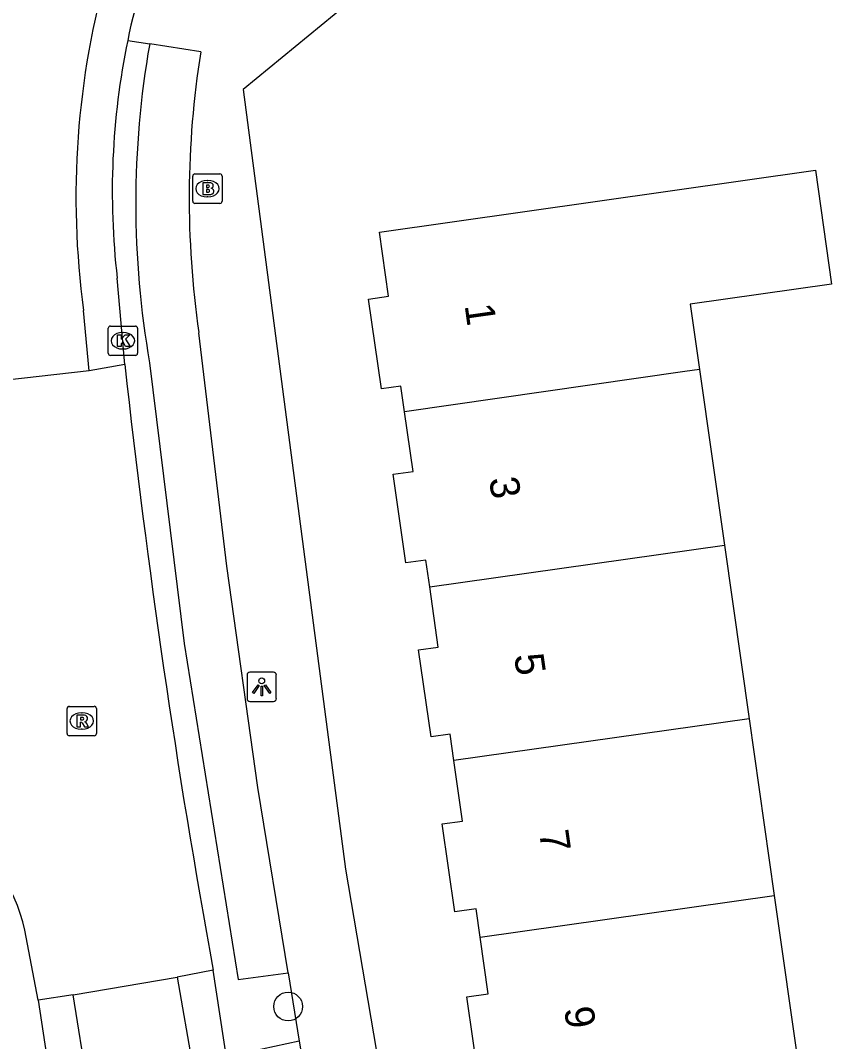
# Model space of a CAD drawing. Extents: x 162074 to 163034, y 381824 to 382557.
# Drawn here: x 162471.78 to 162499.41, y 382456.46 to 382491.25 of the extents above; entities that cross this region are included whole.
import ezdxf

# ---------------------------------------------------------------- set-up
doc = ezdxf.new("R2010")
doc.units = 0
for name, color, linetype in [('IMGEO_Boom', 7, 'Continuous'), ('IMGEO_Brandkraan', 7, 'Continuous'), ('IMGEO_Fietspad_gesloten', 7, 'Continuous'), ('IMGEO_Kolk', 7, 'Continuous'), ('IMGEO_Lichtpunt', 7, 'Continuous'), ('IMGEO_Pand', 7, 'Continuous'), ('IMGEO_Pand_nummerreeks', 7, 'Continuous'), ('IMGEO_Rijbaan_lokaal_open', 7, 'Continuous'), ('IMGEO_Rioolput', 7, 'Continuous'), ('IMGEO_Voetpad_open', 7, 'Continuous')]:
    doc.layers.add(name, color=color, linetype=linetype)

msp = doc.modelspace()

# ---------------------------------------------------------------- linework, layer by layer
at = {"layer": 'IMGEO_Boom'}
msp.add_circle((162480.9, 382457.654), 0.489, dxfattribs=at)
at = {"layer": 'IMGEO_Brandkraan'}
for p, q in [((162477.725, 382486.019), (162478.577, 382486.019)), ((162477.65, 382485.093), (162477.65, 382485.945)), ((162478.138, 382485.799), (162478.163, 382485.799)), ((162478.651, 382485.945), (162478.651, 382485.093)), ((162478.577, 382485.019), (162477.725, 382485.019)), ((162478.161, 382485.239), (162478.136, 382485.239))]:
    msp.add_line(p, q, dxfattribs=at)
for points in [[(162477.725, 382486.019), (162478.577, 382486.019)], [(162477.65, 382485.093), (162477.65, 382485.945)], [(162477.998, 382485.719), (162477.998, 382485.319), (162478.211, 382485.319)], [(162478.229, 382485.719), (162477.998, 382485.719)], [(162478.651, 382485.945), (162478.651, 382485.093)], [(162478.177, 382485.638), (162478.123, 382485.638), (162478.123, 382485.562)], [(162478.123, 382485.562), (162478.176, 382485.562)], [(162478.185, 382485.486), (162478.123, 382485.486), (162478.123, 382485.405)], [(162478.123, 382485.405), (162478.185, 382485.405)], [(162478.577, 382485.019), (162477.725, 382485.019)]]:
    msp.add_lwpolyline(points, dxfattribs=at)
for centre, radius, start, end in [((162477.727, 382485.943), 0.0765, 91.552, 178.448), ((162477.727, 382485.943), 0.0765, 91.552, 178.448), ((162478.575, 382485.943), 0.0765, 1.552, 88.448), ((162478.575, 382485.943), 0.0765, 1.552, 88.448), ((162478.233, 382485.574), 0.145, 59.4692, 91.5367), ((162478.258, 382485.621), 0.0922, 285.5137, 58.1501), ((162478.178, 382485.6), 0.0379, 267.8285, 90.9355), ((162478.186, 382485.445), 0.0404, 269.8759, 90.5077), ((162478.217, 382485.57), 0.251, 268.6676, 293.5347), ((162478.263, 382485.429), 0.105, 301.3115, 78.989), ((162477.727, 382485.095), 0.0765, 181.552, 268.448), ((162477.727, 382485.095), 0.0765, 181.552, 268.448), ((162478.575, 382485.095), 0.0765, 271.552, 358.448), ((162478.575, 382485.095), 0.0765, 271.552, 358.448)]:
    msp.add_arc(centre, radius, start, end, dxfattribs=at)
for centre, major_axis, ratio, start_param, end_param in [((162478.137, 382485.519), (-0.387, 0.002), 0.722429, 4.712389, 7.853982), ((162478.162, 382485.519), (-0.39, 0.002), 0.717154, 1.570796, 4.712389)]:
    msp.add_ellipse(centre, major_axis=major_axis, ratio=ratio, start_param=start_param, end_param=end_param, dxfattribs=at)
at = {"layer": 'IMGEO_Fietspad_gesloten'}
for points in [[(162475.335, 382479.532), (162475.076, 382482.472)], [(162478.823, 382455.767), (162478.345, 382458.898)], [(162472.383, 382457.868), (162472.865, 382454.723)]]:
    msp.add_lwpolyline(points, dxfattribs=at)
for centre, radius, start, end in [((162496.04, 382486.354), 21.033, 145.3205, 168.4412), ((162500.479, 382485.405), 25.571, 168.3507, 186.5854)]:
    msp.add_arc(centre, radius, start, end, dxfattribs=at)
at = {"layer": 'IMGEO_Kolk'}
for p, q in [((162474.846, 382480.837), (162475.698, 382480.837)), ((162474.771, 382479.911), (162474.771, 382480.763)), ((162475.259, 382480.617), (162475.284, 382480.617)), ((162475.772, 382480.763), (162475.772, 382479.911)), ((162475.698, 382479.837), (162474.846, 382479.837)), ((162475.282, 382480.057), (162475.257, 382480.057))]:
    msp.add_line(p, q, dxfattribs=at)
for points in [[(162474.846, 382480.837), (162475.698, 382480.837)], [(162474.771, 382479.911), (162474.771, 382480.763)], [(162475.092, 382480.537), (162475.215, 382480.537), (162475.215, 382480.386), (162475.345, 382480.537), (162475.509, 382480.537), (162475.363, 382480.386), (162475.516, 382480.137), (162475.364, 382480.137), (162475.279, 382480.301), (162475.215, 382480.234), (162475.215, 382480.137), (162475.092, 382480.137), (162475.092, 382480.537)], [(162475.772, 382480.763), (162475.772, 382479.911)], [(162475.698, 382479.837), (162474.846, 382479.837)]]:
    msp.add_lwpolyline(points, dxfattribs=at)
for centre, start, end in [((162474.848, 382480.761), 91.552, 178.448), ((162474.848, 382480.761), 91.552, 178.448), ((162475.696, 382480.761), 1.552, 88.448), ((162475.696, 382480.761), 1.552, 88.448), ((162474.848, 382479.913), 181.552, 268.448), ((162474.848, 382479.913), 181.552, 268.448), ((162475.696, 382479.913), 271.552, 358.448), ((162475.696, 382479.913), 271.552, 358.448)]:
    msp.add_arc(centre, 0.0765, start, end, dxfattribs=at)
for centre, major_axis, ratio, start_param, end_param in [((162475.258, 382480.337), (-0.387, 0.002), 0.722429, 4.712389, 7.853982), ((162475.283, 382480.337), (-0.39, 0.002), 0.717154, 1.570796, 4.712389)]:
    msp.add_ellipse(centre, major_axis=major_axis, ratio=ratio, start_param=start_param, end_param=end_param, dxfattribs=at)
at = {"layer": 'IMGEO_Lichtpunt'}
for p, q in [((162480.403, 382469.046), (162479.595, 382469.046)), ((162480.403, 382469.046), (162479.595, 382469.046)), ((162479.501, 382468.951), (162479.501, 382468.144)), ((162479.501, 382468.951), (162479.501, 382468.144)), ((162480.497, 382468.144), (162480.497, 382468.951)), ((162480.497, 382468.144), (162480.497, 382468.951)), ((162479.595, 382468.05), (162480.403, 382468.05)), ((162479.595, 382468.05), (162480.403, 382468.05))]:
    msp.add_line(p, q, dxfattribs=at)
for points in [[(162479.875, 382468.615), (162479.914, 382468.587), (162479.726, 382468.325), (162479.688, 382468.352), (162479.875, 382468.615)], [(162480.087, 382468.587), (162480.125, 382468.614), (162480.312, 382468.352), (162480.273, 382468.324), (162480.087, 382468.587)], [(162479.977, 382468.567), (162480.024, 382468.567), (162480.024, 382468.245), (162479.977, 382468.245), (162479.977, 382468.567)]]:
    msp.add_lwpolyline(points, dxfattribs=at)
msp.add_circle((162480, 382468.749), 0.0994, dxfattribs=at)
for centre, start, end in [((162479.595, 382468.951), 90, 180), ((162479.595, 382468.951), 90, 180), ((162480.403, 382468.951), 0, 90), ((162480.403, 382468.951), 0, 90), ((162479.595, 382468.144), 180, 270), ((162479.595, 382468.144), 180, 270), ((162480.403, 382468.144), 270, 0), ((162480.403, 382468.144), 270, 360)]:
    msp.add_arc(centre, 0.0946, start, end, dxfattribs=at)
at = {"layer": 'IMGEO_Pand'}
for points in [[(162484.866, 382477.919), (162484.741, 382478.794), (162484.075, 382478.7), (162483.641, 382481.756), (162484.321, 382481.853), (162484.01, 382484.039), (162498.86, 382486.15), (162499.412, 382482.268), (162494.593, 382481.584), (162494.91, 382479.353)], [(162494.91, 382479.353), (162494.414, 382479.294), (162484.866, 382477.919)], [(162494.91, 382479.353), (162495.76, 382473.373)], [(162485.723, 382471.954), (162485.594, 382472.864), (162484.909, 382472.767), (162484.479, 382475.792), (162485.155, 382475.888), (162484.866, 382477.919)], [(162485.723, 382471.954), (162495.76, 382473.373)], [(162495.76, 382473.373), (162496.601, 382467.46)], [(162486.546, 382466.038), (162486.419, 382466.932), (162485.767, 382466.839), (162485.345, 382469.807), (162486.015, 382469.902), (162485.723, 382471.954)], [(162496.601, 382467.46), (162486.546, 382466.038)], [(162496.601, 382467.46), (162497.456, 382461.44)], [(162487.438, 382460.022), (162487.302, 382460.981), (162486.574, 382460.877), (162486.148, 382463.877), (162486.839, 382463.975), (162486.546, 382466.038)], [(162497.456, 382461.44), (162498.317, 382455.386), (162493.216, 382454.661), (162488.265, 382453.957), (162488.104, 382455.085), (162487.413, 382454.987), (162486.987, 382457.985), (162487.713, 382458.088), (162487.438, 382460.022)], [(162487.438, 382460.022), (162497.456, 382461.44)]]:
    msp.add_lwpolyline(points, dxfattribs=at)
at = {"layer": 'IMGEO_Rijbaan_lokaal_open'}
for points in [[(162474.121, 382479.316), (162473.931, 382481.37)], [(162475.335, 382479.532), (162474.121, 382479.316)], [(162474.121, 382479.316), (162470.702, 382478.932)], [(162472.383, 382457.868), (162471.931, 382460.253)], [(162478.345, 382458.898), (162477.114, 382458.653)], [(162473.573, 382458.052), (162477.114, 382458.653)], [(162477.114, 382458.653), (162477.649, 382455.588)], [(162473.573, 382458.052), (162472.383, 382457.868)], [(162474.069, 382455.011), (162473.573, 382458.052)]]:
    msp.add_lwpolyline(points, dxfattribs=at)
for centre, radius, start, end in [((162502.294, 382485.22), 28.623, 164.0274, 187.7291), ((162770.878, 382512.108), 297.333, 186.28999, 190.30906), ((162465.96, 382458.894), 6.124, 12.8212, 97.6244)]:
    msp.add_arc(centre, radius, start, end, dxfattribs=at)
at = {"layer": 'IMGEO_Rioolput'}
for p, q in [((162473.368, 382466.956), (162473.368, 382467.808)), ((162473.443, 382467.882), (162474.295, 382467.882)), ((162473.856, 382467.662), (162473.881, 382467.662)), ((162474.369, 382467.808), (162474.369, 382466.956)), ((162474.295, 382466.882), (162473.443, 382466.882)), ((162473.879, 382467.102), (162473.854, 382467.102))]:
    msp.add_line(p, q, dxfattribs=at)
for points in [[(162473.368, 382466.956), (162473.368, 382467.808)], [(162473.443, 382467.882), (162474.295, 382467.882)], [(162473.957, 382467.58), (162473.705, 382467.582), (162473.705, 382467.182)], [(162474.369, 382467.808), (162474.369, 382466.956)], [(162473.705, 382467.182), (162473.829, 382467.182), (162473.829, 382467.344), (162473.84, 382467.344)], [(162473.883, 382467.501), (162473.829, 382467.501), (162473.829, 382467.42)], [(162473.829, 382467.42), (162473.881, 382467.42)], [(162473.887, 382467.315), (162473.958, 382467.182), (162474.098, 382467.182), (162474.033, 382467.308)], [(162474.295, 382466.882), (162473.443, 382466.882)]]:
    msp.add_lwpolyline(points, dxfattribs=at)
for centre, radius, start, end in [((162473.445, 382467.806), 0.0765, 91.552, 178.448), ((162473.445, 382467.806), 0.0765, 91.552, 178.448), ((162473.956, 382467.47), 0.109, 350.3612, 89.416), ((162474.293, 382467.806), 0.0765, 1.552, 88.448), ((162474.293, 382467.806), 0.0765, 1.552, 88.448), ((162473.839, 382467.291), 0.0533, 26.0293, 88.6989), ((162473.865, 382467.609), 0.19, 274.7715, 282.9687), ((162473.889, 382467.405), 0.0964, 77.0061, 93.1865), ((162473.903, 382467.462), 0.0378, 276.6634, 79.6772), ((162473.954, 382467.47), 0.112, 277.5842, 350.9817), ((162473.938, 382467.255), 0.108, 29.5134, 73.7905), ((162473.445, 382466.958), 0.0765, 181.552, 268.448), ((162473.445, 382466.958), 0.0765, 181.552, 268.448), ((162474.293, 382466.958), 0.0765, 271.552, 358.448), ((162474.293, 382466.958), 0.0765, 271.552, 358.448)]:
    msp.add_arc(centre, radius, start, end, dxfattribs=at)
for centre, major_axis, ratio, start_param, end_param in [((162473.855, 382467.382), (-0.387, 0.002), 0.722429, 4.712389, 7.853982), ((162473.88, 382467.382), (-0.39, 0.002), 0.717154, 1.570796, 4.712389)]:
    msp.add_ellipse(centre, major_axis=major_axis, ratio=ratio, start_param=start_param, end_param=end_param, dxfattribs=at)
at = {"layer": 'IMGEO_Voetpad_open'}
for points in [[(162492.214, 382499.445), (162479.372, 382488.893), (162482.853, 382462.333), (162484.672, 382451.644)], [(162475.434, 382490.568), (162476.183, 382490.451)], [(162477.921, 382490.179), (162476.183, 382490.451)], [(162480.896, 382458.797), (162479.87, 382465.121), (162478.807, 382472.653), (162477.858, 382480.613)], [(162476.181, 382479.584), (162477.362, 382470.026), (162479.199, 382458.577), (162480.896, 382458.797)], [(162480.896, 382458.797), (162481.28, 382456.471)], [(162481.28, 382456.471), (162479.597, 382456.106)]]:
    msp.add_lwpolyline(points, dxfattribs=at)
for centre, radius, start, end in [((162507.087, 382485.012), 31.379, 170.0181, 189.9608), ((162509.528, 382485.188), 31.999, 171.026, 188.2194), ((162881.817, 382522.864), 406.002, 189.41174, 193.67269)]:
    msp.add_arc(centre, radius, start, end, dxfattribs=at)

# ---------------------------------------------------------------- texts
at = {"layer": 'IMGEO_Pand_nummerreeks'}
for s, p in [('1', (162486.909, 382481.543)), ('3', (162487.744, 382475.64)), ('5', (162488.595, 382469.623)), ('7', (162489.446, 382463.607)), ('9', (162490.297, 382457.59))]:
    msp.add_text(s, height=1, rotation=278.0509, dxfattribs=at).set_placement(p)

doc.saveas('drawing.dxf')
